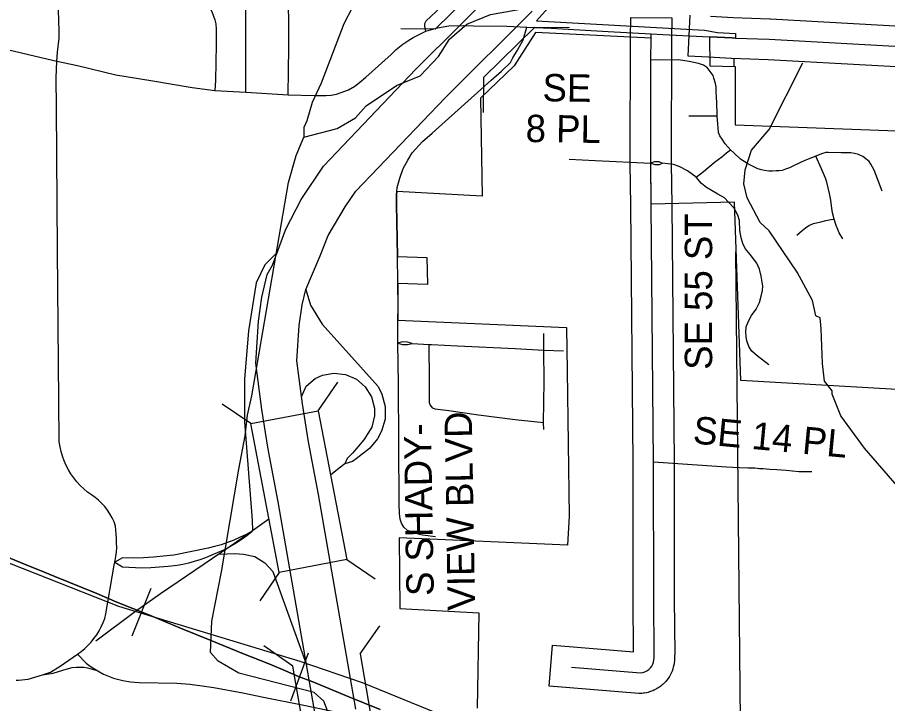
# Model space of a CAD drawing. Extents: x -1403959 to 81668, y -1400582 to 11018.
# Drawn here: x 7684.1 to 7807.2, y 8112.6 to 8209.8 of the extents above; entities that cross this region are included whole.
import ezdxf

# ---------------------------------------------------------------- set-up
doc = ezdxf.new("R2010")
doc.units = 0
for name, color, linetype in [('tdCiCityDivCarto', 7, 'Continuous'), ('tdCiCityStreetTxt', 7, 'Continuous'), ('tdCiCoBndryTxt', 7, 'Continuous'), ('tdCiRRCL', 7, 'Continuous'), ('tdCiSectLine', 7, 'Continuous'), ('tdCiSectNmbr', 7, 'Continuous'), ('tdCiSectTwpRng', 7, 'Continuous'), ('tdCiUABTitleFrame', 7, 'Continuous'), ('tdCoCityStreetMajor', 7, 'Continuous'), ('tdCoDivCarto', 7, 'Continuous'), ('tdCoIntCL', 7, 'Continuous'), ('tdCoSecRteBand', 7, 'Continuous'), ('tdCoSectNmbr', 7, 'Continuous'), ('tdCoSurfBitum', 7, 'Continuous'), ('tdCoSurfEarth', 7, 'Continuous')]:
    doc.layers.add(name, color=color, linetype=linetype)

msp = doc.modelspace()

# ---------------------------------------------------------------- linework, layer by layer
at = {"layer": 'tdCiCityDivCarto'}
for points in [[(7762.18, 8189.69), (7765.83, 8189.5), (7773.7, 8189.1)], [(7737.85, 8175.93), (7737.74, 8183.25), (7737.73, 8184.68), (7737.78, 8185.12)], [(7737.93, 8166.9), (7737.94, 8168.8), (7737.91, 8172.11)], [(7774.1, 8146.86), (7780.3, 8146.4), (7784.45, 8146.15), (7786.2, 8146.02), (7787.48, 8145.98), (7788.45, 8145.98), (7789.08, 8145.92), (7789.6, 8145.92), (7790.57, 8145.83), (7791.54, 8145.75), (7792.86, 8145.67), (7794.67, 8145.5), (7796.51, 8145.5)]]:
    msp.add_lwpolyline(points, dxfattribs=at)
at = {"layer": 'tdCiCityStreetTxt'}
for p, q in [((7726.66, 8154.08), (7729.4, 8158.12)), ((7717.09, 8152.25), (7713.06, 8154.99)), ((7717.09, 8152.25), (7726.66, 8154.08)), ((7726.66, 8154.08), (7730.69, 8133.02)), ((7721.12, 8131.19), (7717.09, 8152.25)), ((7730.69, 8133.02), (7721.12, 8131.19)), ((7730.69, 8133.02), (7730.69, 8133.02)), ((7730.69, 8133.02), (7734.72, 8130.28)), ((7721.12, 8131.19), (7718.38, 8127.16))]:
    msp.add_line(p, q, dxfattribs=at)
at = {"layer": 'tdCiCoBndryTxt'}
for points in [[(7773.77, 8183.65), (7773.7, 8189.1), (7773.7, 8192.28), (7773.73, 8203.71), (7773.75, 8206.8)], [(7782.04, 8207.01), (7785.24, 8206.85), (7785.7, 8206.83)], [(7785.7, 8206.83), (7785.7, 8206.83)], [(7785.7, 8206.83), (7790.48, 8206.66), (7810.8, 8205.53)], [(7762.48, 8117.76), (7772.27, 8116.96), (7772.58, 8117.02), (7772.88, 8117.12), (7773.16, 8117.27), (7773.42, 8117.45), (7773.65, 8117.67), (7773.84, 8117.93), (7773.99, 8118.21), (7774.1, 8118.51), (7774.16, 8118.82), (7774.17, 8119.14), (7774.19, 8119.59), (7774.14, 8127.42), (7774.1, 8146.73), (7774.1, 8146.86), (7773.78, 8183.15), (7773.78, 8183.33)], [(7773.78, 8183.33), (7773.77, 8183.65)]]:
    msp.add_lwpolyline(points, dxfattribs=at)
at = {"layer": 'tdCiRRCL'}
for points in [[(7760.83, 8213.01), (7757.53, 8209.25), (7781.33, 8207.95), (7783.16, 8207.6), (7785.71, 8207.48), (7785.7, 8206.83), (7785.24, 8206.85), (7782.04, 8207.01), (7782.07, 8202.88), (7785.66, 8202.79), (7785.65, 8194.55), (7809.8, 8193.67)], [(7810.19, 8156.97), (7786.45, 8158.35), (7785.54, 8183.58), (7773.78, 8183.33), (7773.7, 8189.1), (7773.7, 8192.28), (7773.73, 8203.71), (7773.75, 8206.8), (7757.4, 8207.61), (7754.38, 8202.9), (7749.61, 8198.34), (7749.83, 8184.45), (7737.78, 8185.12), (7737.73, 8184.68), (7737.74, 8183.25), (7737.85, 8175.93), (7742.03, 8175.78), (7742.09, 8171.96), (7737.91, 8172.11), (7737.93, 8166.9), (7761.79, 8165.87), (7761.9, 8159.71), (7762.16, 8139.15), (7761.92, 8135.03), (7738.12, 8136.09), (7738.21, 8126.08), (7749.38, 8125.48), (7749.14, 8111.97)]]:
    msp.add_lwpolyline(points, dxfattribs=at)
at = {"layer": 'tdCiSectLine'}
for points in [[(7782.18, 8209.91), (7785.36, 8209.75), (7790.58, 8209.56), (7790.64, 8209.56), (7821.71, 8207.83), (7821.71, 8207.83), (7833.69, 8207.14), (7836.51, 8207.14), (7836.51, 8207), (7845.75, 8206.52), (7845.76, 8206.63), (7848.57, 8206.38), (7852.38, 8206.23), (7852.41, 8206.23), (7878.82, 8204.92), (7878.7, 8224.63)], [(7831.43, 8106.97), (7831.06, 8120.12), (7831.06, 8120.18), (7830.67, 8192.4), (7830.67, 8192.42), (7830.67, 8192.42), (7830.7, 8201.49), (7830.56, 8201.49), (7830.56, 8201.51), (7821.38, 8202.04), (7790.35, 8203.76), (7785.13, 8203.95), (7785.09, 8203.95), (7781.9, 8204.11), (7779, 8204.25), (7779.28, 8210.05)], [(7772.27, 8114.06), (7772.08, 8114.06), (7772.03, 8114.07), (7762.24, 8114.87), (7759.35, 8115.11), (7759.82, 8120.89), (7762.71, 8120.65), (7771.29, 8119.95), (7771.24, 8127.4), (7771.24, 8127.41), (7771.2, 8146.72), (7770.88, 8183.12), (7770.8, 8189.06), (7770.8, 8189.1), (7770.8, 8192.28), (7770.8, 8192.28), (7770.82, 8203.72), (7770.82, 8203.73), (7770.85, 8206.83), (7770.87, 8209.73), (7776.68, 8209.68), (7776.65, 8206.78), (7776.63, 8203.69), (7776.6, 8192.27), (7776.6, 8189.11), (7776.68, 8183.19), (7776.68, 8183.18), (7777, 8146.76), (7777, 8146.74), (7777.04, 8127.43), (7777.1, 8119.61), (7777.1, 8119.59), (7777.09, 8119.47), (7777.07, 8119.02), (7777.07, 8119), (7777.06, 8118.68), (7777.06, 8118.63), (7777.04, 8118.44), (7777.01, 8118.25), (7777.01, 8118.25), (7776.94, 8117.94), (7776.9, 8117.76), (7776.85, 8117.57), (7776.83, 8117.52), (7776.72, 8117.22), (7776.67, 8117.1), (7776.59, 8116.92), (7776.54, 8116.83), (7776.39, 8116.55), (7776.35, 8116.48), (7776.25, 8116.32), (7776.16, 8116.18), (7775.97, 8115.93), (7775.95, 8115.91), (7775.83, 8115.76), (7775.7, 8115.62), (7775.68, 8115.6), (7775.45, 8115.38), (7775.33, 8115.27), (7775.19, 8115.15), (7775.12, 8115.1), (7774.86, 8114.91), (7774.78, 8114.85), (7774.61, 8114.75), (7774.5, 8114.69), (7774.21, 8114.54), (7774.16, 8114.52), (7773.99, 8114.44), (7773.81, 8114.37), (7773.51, 8114.27), (7773.33, 8114.21), (7773.15, 8114.17), (7773.09, 8114.16), (7772.78, 8114.1), (7772.65, 8114.08), (7772.46, 8114.06), (7772.27, 8114.06)]]:
    msp.add_lwpolyline(points, dxfattribs=at)
at = {"layer": 'tdCiSectNmbr'}
for points in [[(7689.64, 8203.57), (7689.75, 8204.82), (7689.99, 8206.83), (7689.99, 8207.75), (7689.92, 8209.34), (7689.82, 8212.21), (7689.72, 8218.07), (7689.72, 8218.97), (7689.64, 8225.01), (7689.67, 8234.17), (7689.63, 8243.01)], [(7670.31, 8208.13), (7686.64, 8204.28)], [(7737.66, 8205.2), (7738.64, 8205.97), (7739.31, 8206.43), (7740.07, 8206.89), (7741.89, 8207.79)], [(7737.78, 8185.12), (7737.84, 8185.68), (7738.2, 8187.01), (7738.67, 8188.36), (7739.31, 8189.54), (7739.95, 8190.58), (7741.4, 8192.2), (7742.77, 8193.38), (7749.66, 8199.55), (7751.11, 8200.87), (7752.58, 8202.13), (7753.86, 8203.39), (7754.19, 8204.01), (7754.84, 8205.14), (7755.63, 8206.59), (7756.16, 8208.39)], [(7741.89, 8207.79), (7743.55, 8208.28), (7745.15, 8208.56), (7747.16, 8208.59), (7748.61, 8208.56), (7753.35, 8208.53), (7756.16, 8208.39), (7759.63, 8208.22), (7767.7, 8207.78), (7773.76, 8207.42)], [(7773.75, 8206.8), (7773.76, 8207.42)], [(7773.76, 8207.42), (7775.44, 8207.33), (7782.01, 8207.01)], [(7782.01, 8207.01), (7782.02, 8207.01)], [(7692.59, 8202.93), (7698.01, 8201.64), (7702.95, 8200.8), (7708.79, 8199.82), (7712, 8199.43), (7712.03, 8199.43), (7716.38, 8199.15), (7722.38, 8198.8), (7726.13, 8198.71), (7727.78, 8198.7), (7728.48, 8198.76), (7729.23, 8198.91), (7730.94, 8199.51), (7731.81, 8200.04), (7732.47, 8200.54), (7733.37, 8201.28), (7736.95, 8204.52), (7737.66, 8205.2)], [(7686.64, 8204.28), (7689.64, 8203.57)], [(7689.58, 8197.01), (7689.55, 8201.19), (7689.64, 8203.57)], [(7689.64, 8203.57), (7692.59, 8202.93)], [(7690, 8149.67), (7689.94, 8155.53), (7689.75, 8176.74), (7689.58, 8197.01)], [(7737.91, 8172.11), (7737.91, 8172.32), (7737.85, 8175.93)], [(7692.58, 8119.6), (7693.1, 8119.99), (7693.6, 8120.41), (7694.06, 8120.86), (7694.5, 8121.34), (7694.91, 8121.84), (7695.29, 8122.37), (7695.63, 8122.92), (7695.94, 8123.49), (7696.22, 8124.08), (7696.45, 8124.69), (7696.57, 8125.32), (7697.77, 8132.2), (7697.91, 8132.86), (7698.02, 8133.46), (7698.1, 8134.08), (7698.14, 8134.73), (7698.11, 8135.34), (7698.08, 8136), (7698.06, 8136.59), (7698.02, 8137.17), (7697.93, 8137.76), (7697.75, 8138.35), (7697.48, 8138.92), (7697.17, 8139.47), (7696.82, 8140), (7696.43, 8140.5), (7696.01, 8140.96), (7695.55, 8141.4), (7695.06, 8141.8), (7694.54, 8142.16), (7693.98, 8142.57), (7693.45, 8143.02), (7692.95, 8143.5), (7692.48, 8144.01), (7692.04, 8144.56), (7691.64, 8145.13), (7691.28, 8145.73), (7690.96, 8146.34), (7690.68, 8146.98), (7690.45, 8147.64), (7690.25, 8148.31), (7690.11, 8148.99), (7690, 8149.67)], [(7683.89, 8115.95), (7684.23, 8115.94), (7685.59, 8116.08), (7687.62, 8116.68), (7688.73, 8117.08), (7690.12, 8117.92), (7692.58, 8119.6)], [(7692.58, 8119.6), (7693.79, 8118.37), (7694.37, 8117.92), (7695.38, 8117.29), (7695.46, 8117.24), (7696.27, 8116.81), (7697.68, 8116.21), (7699, 8115.87), (7700.08, 8115.72), (7701.28, 8115.63), (7706.64, 8115.51), (7708.46, 8115.36), (7710.23, 8115.15), (7711.89, 8114.88), (7715.96, 8114.14), (7718.91, 8113.54), (7724.62, 8112.4), (7726.86, 8111.94), (7728.86, 8111.52), (7732.55, 8110.44), (7742.68, 8106.48), (7751.83, 8102.73)], [(7687.62, 8116.68), (7689.11, 8116.92), (7690.48, 8117.34), (7691.3, 8117.61), (7691.84, 8117.71), (7692.38, 8117.78), (7692.92, 8117.8), (7693.47, 8117.77), (7694.01, 8117.7), (7695.38, 8117.29)]]:
    msp.add_lwpolyline(points, dxfattribs=at)
at = {"layer": 'tdCiSectTwpRng'}
for points in [[(7722.38, 8198.8), (7722.46, 8202.19), (7722.47, 8205.47), (7722.44, 8215.1), (7722.43, 8216.87), (7722.47, 8219.33), (7722.46, 8220.81), (7722.32, 8222.25), (7722.15, 8223.64), (7722.12, 8224.93), (7722.09, 8227.13), (7722.03, 8228.65), (7722.1, 8232.47), (7722.03, 8234.59), (7722.07, 8238.9), (7722.01, 8240.43), (7722.06, 8244.23), (7721.96, 8250.18), (7722.03, 8253.52), (7721.83, 8254.78), (7721.41, 8256.17), (7720.58, 8257.63)], [(7716.38, 8199.15), (7716.39, 8216.91), (7716.42, 8220.26), (7716.36, 8222.08), (7716.16, 8223.75)], [(7709.42, 8213.15), (7709.88, 8212.67), (7710.26, 8212.29), (7710.94, 8211.58), (7711.31, 8211.09), (7711.59, 8210.57), (7711.84, 8209.94), (7712.01, 8209.41), (7712.15, 8208.85), (7712.2, 8208.09), (7712.22, 8205.93), (7712.09, 8200.8), (7712.03, 8199.43)], [(7741.89, 8207.79), (7741.73, 8208.53), (7741.75, 8208.9), (7741.94, 8209.26), (7743.99, 8211.21)], [(7783.15, 8195.23), (7783.11, 8195.83), (7783.11, 8196.23), (7783.08, 8197.43), (7783.02, 8198.69), (7782.99, 8199), (7782.96, 8199.41), (7782.96, 8199.94), (7782.86, 8200.41), (7782.64, 8201.15), (7782.52, 8201.54), (7781.7, 8202.64), (7781.6, 8202.7), (7781.17, 8202.99), (7780.48, 8203.21), (7779.16, 8203.52), (7777.65, 8203.74), (7773.73, 8203.71)], [(7779.11, 8195.8), (7780.07, 8195.83), (7783.11, 8195.83)], [(7783.19, 8194.68), (7783.15, 8195.23)], [(7806.46, 8185.15), (7805.82, 8186.92), (7805.57, 8187.53), (7805.32, 8188.11), (7805.11, 8188.55), (7804.86, 8189), (7804.61, 8189.34), (7804.16, 8189.73), (7803.71, 8190.05), (7803.12, 8190.35), (7802.55, 8190.51), (7802.02, 8190.57), (7800.66, 8190.59), (7798.83, 8190.63), (7798.47, 8190.61), (7797.88, 8190.46), (7797.09, 8190.12), (7795.53, 8189.49), (7794.03, 8188.79), (7793.37, 8188.45), (7792.79, 8188.25), (7792.33, 8188.09), (7791.9, 8188.04), (7791.47, 8188.02), (7790.96, 8187.99), (7790.41, 8187.99), (7789.82, 8188.07), (7789.38, 8188.17), (7788.86, 8188.3), (7788.51, 8188.5), (7787.43, 8189.05), (7786.39, 8189.71), (7785.46, 8190.57), (7785.01, 8191.01), (7784.26, 8191.87), (7783.83, 8192.5), (7783.5, 8193.01), (7783.29, 8193.46), (7783.23, 8194.14), (7783.19, 8194.68)], [(7782.67, 8189.21), (7782.73, 8189.26), (7783.77, 8190.03), (7784.45, 8190.57), (7785.01, 8191.01)], [(7775.34, 8189.14), (7774.92, 8189.33), (7774.26, 8189.32), (7773.7, 8189.1)], [(7773.7, 8189.1), (7774.27, 8188.93), (7774.97, 8188.94), (7775.34, 8189.14)], [(7784.75, 8183.57), (7784.7, 8183.61), (7784.16, 8184.2), (7783.2, 8184.74), (7782.4, 8185.2), (7781.6, 8185.68), (7780.9, 8186.26), (7780.14, 8187.15), (7778.93, 8188.04), (7777.73, 8188.65), (7776.93, 8188.91), (7775.34, 8189.14)], [(7780.14, 8187.15), (7781.18, 8187.93), (7782.67, 8189.21)], [(7800.9, 8178.39), (7800.39, 8179.27), (7800.17, 8179.74), (7799.96, 8180.28), (7799.66, 8181.21), (7799.45, 8182.09), (7799.31, 8183.09), (7799.2, 8183.87), (7799.01, 8184.83), (7798.84, 8185.65), (7798.62, 8186.42), (7798.42, 8187.01), (7797.86, 8188.33), (7797.09, 8190.12)], [(7784.78, 8183.54), (7784.75, 8183.57)], [(7790.41, 8160.57), (7788.76, 8161.83), (7788.03, 8162.52), (7787.61, 8163.15), (7787.31, 8163.98), (7787.22, 8164.57), (7787.16, 8165.24), (7787.2, 8165.96), (7787.53, 8166.76), (7787.96, 8167.54), (7788.63, 8168.47), (7789.09, 8169.39), (7789.33, 8170.28), (7789.52, 8171.12), (7789.55, 8171.78), (7789.48, 8172.28), (7789.35, 8173.14), (7789.11, 8174.12), (7788.7, 8174.97), (7787.79, 8176.18), (7787.07, 8177.03), (7786.74, 8177.75), (7786.51, 8178.57), (7786.33, 8179.57), (7786.27, 8181.01), (7786.03, 8181.77), (7785.66, 8182.46)], [(7794.37, 8178.94), (7795.12, 8179.61), (7795.62, 8179.98), (7796.08, 8180.31), (7796.73, 8180.56), (7797.8, 8180.8), (7798.51, 8180.99), (7799.19, 8181.14), (7799.66, 8181.21)], [(7737.99, 8157.89), (7737.93, 8163.66), (7737.92, 8163.9), (7737.93, 8166.9)], [(7758.57, 8151.42), (7758.52, 8152.36), (7758.63, 8158.24), (7758.6, 8162.66), (7758.59, 8165.02)], [(7739.95, 8163.59), (7739.3, 8163.8), (7738.54, 8163.83), (7737.93, 8163.66)], [(7737.93, 8163.66), (7738.58, 8163.46), (7739.3, 8163.45), (7739.95, 8163.59)], [(7739.95, 8163.59), (7742.36, 8163.46), (7742.69, 8163.44), (7746.34, 8163.26), (7754.53, 8162.87), (7758.6, 8162.66), (7761.34, 8162.54)], [(7758.52, 8152.36), (7754.52, 8152.77), (7749.35, 8153.46), (7745.12, 8154.05), (7743.96, 8154.2), (7743.2, 8154.31), (7742.88, 8154.46), (7742.66, 8154.66), (7742.51, 8154.92), (7742.4, 8155.2), (7742.38, 8158.3), (7742.36, 8163.46)], [(7743.24, 8136.21), (7741.42, 8136.47), (7740.96, 8136.57), (7740.37, 8136.75), (7739.29, 8137.14), (7738.74, 8137.59), (7738.45, 8138.15), (7738.25, 8138.75), (7738.15, 8139.52), (7738.1, 8140.88), (7737.99, 8157.88), (7737.99, 8157.89)], [(7697.86, 8132.64), (7698.96, 8131.99), (7701.7, 8131.85), (7702.95, 8131.88), (7704.19, 8131.96), (7705.43, 8132.07), (7706.67, 8132.23), (7707.5, 8132.38), (7708.32, 8132.57), (7709.13, 8132.79), (7709.93, 8133.04), (7710.72, 8133.32), (7711.5, 8133.64), (7712.39, 8134), (7713.27, 8134.4), (7714.12, 8134.84), (7714.95, 8135.33), (7715.75, 8135.86), (7716.53, 8136.42), (7717.28, 8137.03)], [(7717.28, 8137.03), (7716.44, 8136.58), (7715.58, 8136.16), (7714.7, 8135.78), (7713.81, 8135.43), (7712.9, 8135.12), (7711.98, 8134.85), (7711.06, 8134.62), (7706.2, 8133.65), (7704.77, 8133.47), (7703.34, 8133.33), (7701.91, 8133.24), (7700.47, 8133.19), (7698.96, 8133.27), (7697.86, 8132.64)]]:
    msp.add_lwpolyline(points, dxfattribs=at)
at = {"layer": 'tdCiUABTitleFrame'}
msp.add_lwpolyline([(7785.66, 8182.46), (7785.48, 8182.81), (7784.78, 8183.54)], dxfattribs=at)
at = {"layer": 'tdCoCityStreetMajor'}
for points in [[(7785.51, 8202.79), (7785.5, 8203.97)], [(7786.4, 8110.17), (7785.76, 8176.56)]]:
    msp.add_lwpolyline(points, dxfattribs=at)
at = {"layer": 'tdCoDivCarto'}
for points in [[(7726.24, 8110.83), (7720.99, 8141.16), (7719.54, 8148.65), (7718.65, 8154.26), (7717.82, 8160.82), (7718.17, 8166.76), (7718.65, 8170.16), (7719.43, 8173.35), (7720.16, 8174.67), (7722.08, 8179.8), (7724.25, 8183.96), (7727.38, 8188.71), (7740.48, 8202.43), (7752.88, 8214.77)], [(7731.96, 8111.83), (7726.7, 8142.22), (7725.25, 8149.69), (7724.4, 8155.05), (7723.63, 8161.12), (7723.94, 8166.12), (7724.36, 8169.06), (7724.89, 8171.22), (7726.91, 8175.99), (7728.05, 8178.87), (7730.48, 8182.95), (7731.98, 8185.15), (7744.63, 8198.37), (7756.94, 8210.62)]]:
    msp.add_lwpolyline(points, dxfattribs=at)
at = {"layer": 'tdCoIntCL'}
for points in [[(7720.86, 8176.52), (7719.1, 8174.72), (7717.86, 8172.17), (7716.78, 8165.4), (7716.21, 8158.55), (7716.23, 8152.52), (7717.28, 8138.61), (7717.33, 8137.08)], [(7724.89, 8171.22), (7725.53, 8169.02), (7727.18, 8166.35), (7735.15, 8157.53), (7735.67, 8156.44), (7736.11, 8154.7), (7736.1, 8152.9), (7735.58, 8151.18), (7735.02, 8150.12), (7733.88, 8148.73), (7732.02, 8147.28), (7731.52, 8146.91), (7730.39, 8146.55), (7729.63, 8145.93), (7728.4, 8144.98)], [(7724.27, 8156.06), (7724.96, 8157.54), (7726.23, 8158.62), (7727.23, 8159.1), (7728.87, 8159.39), (7730.52, 8159.2), (7732.04, 8158.53), (7733.31, 8157.45), (7734.2, 8156.05), (7734.63, 8154.45), (7734.63, 8153.35), (7734.21, 8151.74), (7733.12, 8149.94), (7731.5, 8148.06), (7730.76, 8147.32), (7730.39, 8146.55)], [(7719.67, 8138.74), (7717.33, 8137.08), (7714.16, 8134.85), (7704.31, 8128.15), (7700.8, 8125.65), (7695.19, 8121.45)], [(7712.57, 8133.78), (7714.84, 8133.86), (7716.09, 8133.77), (7717.66, 8133.44), (7719.09, 8132.56), (7720.23, 8131.33), (7724.98, 8118.11)]]:
    msp.add_lwpolyline(points, dxfattribs=at)
at = {"layer": 'tdCoSecRteBand'}
for p, q in [((7700.29, 8122.23), (7703, 8128.96)), ((7722.75, 8113.01), (7725.28, 8119.81))]:
    msp.add_line(p, q, dxfattribs=at)
for points in [[(7655.03, 8141.41), (7666.17, 8139.09), (7698.4, 8126.41), (7724.04, 8118.62), (7732.87, 8115.61), (7750.31, 8108.5), (7790.81, 8091.48)], [(7735.4, 8111.79), (7730.98, 8113.6), (7725.88, 8115.72), (7723.86, 8116.47), (7722.02, 8117.27), (7719.78, 8118.22), (7715.83, 8119.77), (7711.57, 8121.5), (7707.15, 8123.29), (7702.66, 8125.19), (7698.15, 8127), (7695.32, 8128.19), (7689.36, 8130.63), (7687.77, 8131.27), (7685.09, 8132.36), (7680.34, 8134.3)], [(7680.34, 8134.3), (7685.09, 8132.36), (7687.77, 8131.27), (7689.36, 8130.63), (7695.32, 8128.19), (7698.15, 8127), (7702.66, 8125.19), (7707.15, 8123.29), (7711.57, 8121.5), (7715.83, 8119.77), (7719.78, 8118.22), (7722.02, 8117.27), (7723.86, 8116.47), (7725.88, 8115.72), (7730.98, 8113.6), (7735.4, 8111.79)]]:
    msp.add_lwpolyline(points, dxfattribs=at)
at = {"layer": 'tdCoSurfBitum'}
for points in [[(7761.89, 8271.27), (7763.41, 8265.31), (7763.41, 8256.92), (7763.1, 8255.08), (7761.73, 8251.57), (7759.43, 8247.76), (7757.3, 8245.62), (7755.61, 8243.49), (7752.41, 8241.35), (7750.42, 8239.67), (7746.45, 8230.67), (7745.68, 8225.47), (7741.25, 8216.93), (7738.65, 8214.49), (7731.47, 8211.13), (7730.25, 8208.84), (7727.04, 8200.45), (7725.81, 8197.7), (7725.05, 8195.1), (7724.59, 8194.19), (7724.59, 8192.81)], [(7724.59, 8192.81), (7729.32, 8194.03), (7731.92, 8195.56), (7733.45, 8197.24), (7737.73, 8200.13), (7741.09, 8201.5), (7743.69, 8204.24), (7745.22, 8206.68), (7747.66, 8208.81), (7751.02, 8210.18), (7762.18, 8212.14), (7764.93, 8213.82), (7766.15, 8215.04), (7771.04, 8218.08), (7780.82, 8224.78), (7784.64, 8226.91), (7786.17, 8227.36), (7790.45, 8227.66), (7792.43, 8227.18), (7799.78, 8227.13), (7802.83, 8227.74)], [(7808.57, 8143.46), (7803.98, 8148.8), (7800.62, 8153.38), (7799.39, 8156.43), (7799.39, 8156.89), (7798.32, 8158.28), (7798.01, 8160.75), (7797.84, 8165.68), (7797.68, 8167.22), (7797.07, 8167.53), (7796.6, 8169.69), (7794.45, 8173.7), (7790.46, 8179.56), (7789.19, 8180.71), (7787.35, 8184.22), (7786.9, 8186.21), (7787.05, 8188.19), (7787.97, 8190.94), (7790.46, 8193.91), (7795.22, 8203.31)], [(7731.88, 8095.55), (7731.88, 8098.14), (7730.2, 8101.66), (7730.05, 8104.86), (7728.68, 8108.68), (7728.37, 8110.51), (7727.46, 8112.96), (7726.08, 8114.18), (7715.39, 8116.93), (7712.49, 8118.62), (7711.42, 8119.84), (7711.58, 8124.27), (7712.96, 8131.29), (7715.41, 8145.79), (7716.32, 8150.53), (7716.63, 8153.43), (7717.24, 8156.17), (7722.45, 8186.4), (7723.52, 8190.22), (7724.59, 8192.81)]]:
    msp.add_lwpolyline(points, dxfattribs=at)
at = {"layer": 'tdCoSurfEarth'}
for p, q in [((7743.21, 8208.11), (7750.48, 8215.23)), ((7743.21, 8208.11), (7738.34, 8208.16)), ((7757.31, 8208.39), (7750.04, 8201.25)), ((7757.31, 8208.39), (7762.19, 8208.34)), ((7750.04, 8201.25), (7749.99, 8196.28)), ((7732.56, 8119.66), (7735.37, 8123.64)), ((7723.04, 8117.94), (7718.97, 8120.8)), ((7732.56, 8119.66), (7734.29, 8109.64)), ((7724.77, 8107.9), (7723.04, 8117.94))]:
    msp.add_line(p, q, dxfattribs=at)

# ---------------------------------------------------------------- texts
at = {"layer": 'tdCoSectNmbr'}
for s, rotation, p in [('SE', 359.2162, (7758.37, 8197.89)), ('8 PL', 359.2162, (7755.98, 8192.12)), ('SE 55 ST', 90, (7782.4, 8159.87)), ('VIEW BLVD', 90.9569, (7748.85, 8125.83)), ('S SHADY-', 90.9569, (7743.01, 8127.89)), ('SE 14 PL', 354.6062, (7779.58, 8149.47))]:
    msp.add_text(s, height=3.869, rotation=rotation, dxfattribs=at).set_placement(p)

doc.saveas('drawing.dxf')
